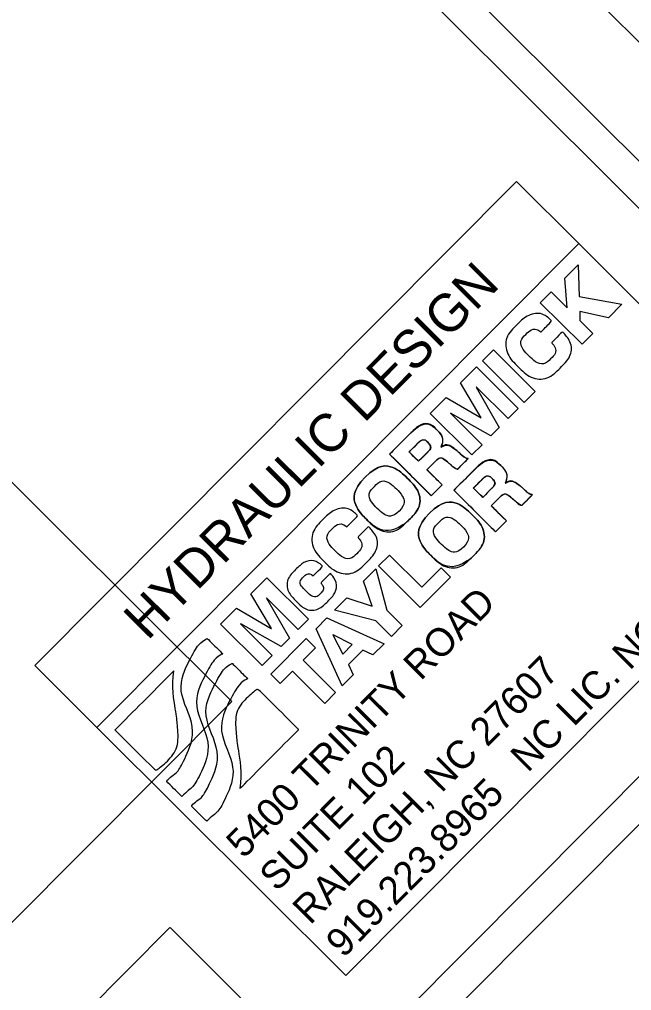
# Model space of a CAD drawing. Extents: x 1481763 to 1495577, y 493394 to 506245.
# Drawn here: x 1489913.5 to 1490186.2, y 499343.7 to 499776.1 of the extents above; entities that cross this region are included whole.
import ezdxf

# ---------------------------------------------------------------- set-up
doc = ezdxf.new("R2010")
doc.units = 0
for name, color, linetype in [('Prop Grid Mask', 7, 'Continuous'), ('Prop Horizontal Alignment Curve and Spiral Data', 7, 'Continuous'), ('Scratch_Level_4', 7, 'Continuous'), ('Sheet Plot Border Inside CELL', 7, 'Continuous'), ('Sheet Sticker Exception Certification CELL', 7, 'Continuous'), ('Sheet Title CELL', 7, 'Continuous')]:
    doc.layers.add(name, color=color, linetype=linetype)

msp = doc.modelspace()

# ---------------------------------------------------------------- linework, layer by layer
at = {"layer": 'Prop Grid Mask'}
for p, q in [((1490156.42, 499660.88), (1490162.4, 499666.89)), ((1490162.4, 499666.89), (1490162.87, 499652.75)), ((1490157.46, 499647.68), (1490156.42, 499660.88)), ((1490145.52, 499649.94), (1490150.34, 499654.78)), ((1490150.34, 499654.78), (1490157.46, 499647.68)), ((1490162.87, 499652.75), (1490181.82, 499649.26)), ((1490164.08, 499631.45), (1490145.52, 499649.94)), ((1490181.82, 499649.26), (1490175.84, 499643.26)), ((1490175.84, 499643.26), (1490163.07, 499646.03)), ((1490163.07, 499646.03), (1490163.18, 499641.99)), ((1490163.18, 499641.99), (1490168.9, 499636.29)), ((1490168.9, 499636.29), (1490164.08, 499631.45)), ((1490119.78, 499624.1), (1490124.6, 499628.93)), ((1490124.6, 499628.93), (1490143.16, 499610.44)), ((1490138.35, 499605.61), (1490119.78, 499624.1)), ((1490110, 499614.26), (1490117.09, 499621.39)), ((1490117.09, 499621.39), (1490135.65, 499602.9)), ((1490119.19, 499598.74), (1490110, 499614.26)), ((1490117.03, 499612.39), (1490116.98, 499612.33)), ((1490116.98, 499612.33), (1490127.19, 499594.4)), ((1490131.12, 499598.35), (1490117.03, 499612.39)), ((1490143.16, 499610.44), (1490138.35, 499605.61)), ((1490096.48, 499600.69), (1490103.58, 499607.82)), ((1490103.58, 499607.82), (1490119.13, 499598.69)), ((1490115.04, 499582.21), (1490096.48, 499600.69)), ((1490105.54, 499600.84), (1490105.48, 499600.79)), ((1490105.48, 499600.79), (1490119.57, 499586.76)), ((1490123.51, 499590.71), (1490105.54, 499600.84)), ((1490135.65, 499602.9), (1490131.12, 499598.35)), ((1490119.13, 499598.69), (1490119.19, 499598.74)), ((1490127.19, 499594.4), (1490123.51, 499590.71)), ((1490101.29, 499585.76), (1490101.34, 499585.71)), ((1490119.57, 499586.76), (1490115.04, 499582.21)), ((1490113.44, 499580.59), (1490108.67, 499575.81)), ((1490129.91, 499569.68), (1490129.96, 499569.63)), ((1490142.06, 499564.52), (1490137.29, 499559.74)), ((1490073.45, 499532.76), (1490078.27, 499537.59)), ((1490078.27, 499537.59), (1490092.67, 499523.25)), ((1490066.72, 499525.99), (1490072.18, 499531.48)), ((1490072.18, 499531.48), (1490077.1, 499513.12)), ((1490092.02, 499514.27), (1490073.45, 499532.76)), ((1490092.67, 499523.25), (1490101.3, 499531.91)), ((1490101.3, 499531.91), (1490105.45, 499527.76)), ((1490016.54, 499520.42), (1490023.64, 499527.55)), ((1490023.64, 499527.55), (1490042.2, 499509.06)), ((1490105.45, 499527.76), (1490092.02, 499514.27)), ((1490070.58, 499514.79), (1490066.72, 499525.99)), ((1490025.73, 499504.9), (1490016.54, 499520.42)), ((1490023.58, 499518.54), (1490023.53, 499518.49)), ((1490023.53, 499518.49), (1490033.73, 499500.56)), ((1490037.67, 499504.51), (1490023.58, 499518.54)), ((1490053.9, 499513.12), (1490059.37, 499518.61)), ((1490059.37, 499518.61), (1490070.58, 499514.79)), ((1490003.03, 499506.85), (1490010.12, 499513.98)), ((1490010.12, 499513.98), (1490025.68, 499504.85)), ((1490045.61, 499504.79), (1490050.5, 499509.71)), ((1490050.5, 499509.71), (1490075.98, 499498.16)), ((1490072.28, 499508.28), (1490053.9, 499513.12)), ((1490077.1, 499513.12), (1490084.01, 499506.23)), ((1490021.59, 499488.37), (1490003.03, 499506.85)), ((1490012.08, 499507), (1490012.03, 499506.95)), ((1490012.03, 499506.95), (1490026.12, 499492.92)), ((1490030.06, 499496.87), (1490012.08, 499507)), ((1490025.68, 499504.85), (1490025.73, 499504.9)), ((1490042.2, 499509.06), (1490037.67, 499504.51)), ((1490079.2, 499501.4), (1490072.28, 499508.28)), ((1490084.01, 499506.23), (1490079.2, 499501.4)), ((1490033.73, 499500.56), (1490030.06, 499496.87)), ((1490057.26, 499479.37), (1490045.61, 499504.79)), ((1490053.22, 499502.14), (1490053.16, 499502.09)), ((1490053.16, 499502.09), (1490057.57, 499493.51)), ((1490061.76, 499497.72), (1490053.22, 499502.14)), ((1490025.44, 499484.54), (1490041.28, 499500.45)), ((1490045.44, 499496.31), (1490039.93, 499490.77)), ((1490041.28, 499500.45), (1490045.44, 499496.31)), ((1490057.57, 499493.51), (1490061.76, 499497.72)), ((1490075.98, 499498.16), (1490070.95, 499493.12)), ((1490026.12, 499492.92), (1490021.59, 499488.37)), ((1490066.49, 499495.29), (1490060.04, 499488.82)), ((1490070.95, 499493.12), (1490066.49, 499495.29)), ((1490039.93, 499490.77), (1490054.33, 499476.42)), ((1490060.04, 499488.82), (1490062.2, 499484.33)), ((1490029.59, 499480.39), (1490025.44, 499484.54)), ((1490035.11, 499485.93), (1490029.59, 499480.39)), ((1490049.51, 499471.59), (1490035.11, 499485.93)), ((1490062.2, 499484.33), (1490057.26, 499479.37)), ((1490054.33, 499476.42), (1490049.51, 499471.59))]:
    msp.add_line(p, q, dxfattribs=at)
for points in [[(1489948.05, 499460.86), (1490162.62, 499676.33), (1490134.88, 499703.95), (1489920.31, 499488.48)], [(1489948.05, 499460.86), (1490162.62, 499676.33), (1490273.45, 499565.96), (1490058.87, 499350.49)]]:
    msp.add_lwpolyline(points, close=True, dxfattribs=at)
for points in [[(1490145.52, 499649.94), (1490150.34, 499654.78), (1490157.46, 499647.68), (1490156.42, 499660.88), (1490162.4, 499666.89), (1490162.87, 499652.75), (1490181.82, 499649.26), (1490175.84, 499643.26), (1490163.07, 499646.03), (1490163.18, 499641.99), (1490168.9, 499636.29), (1490164.08, 499631.45), (1490145.52, 499649.94)], [(1490119.78, 499624.1), (1490124.6, 499628.93), (1490143.16, 499610.44), (1490138.35, 499605.61), (1490119.78, 499624.1)], [(1490096.48, 499600.69), (1490103.58, 499607.82), (1490119.13, 499598.69), (1490119.19, 499598.74), (1490110, 499614.26), (1490117.09, 499621.39), (1490135.65, 499602.9), (1490131.12, 499598.35), (1490117.03, 499612.39), (1490116.98, 499612.33), (1490127.19, 499594.4), (1490123.51, 499590.71), (1490105.54, 499600.84), (1490105.48, 499600.79), (1490119.57, 499586.76), (1490115.04, 499582.21), (1490096.48, 499600.69)], [(1490098.68, 499579.29), (1490095.03, 499575.63), (1490101.79, 499568.89), (1490096.97, 499564.06), (1490078.41, 499582.55), (1490087.83, 499592.01)], [(1490090.93, 499587.37), (1490087.1, 499583.52), (1490091.28, 499579.35), (1490095.32, 499583.41)], [(1490127.3, 499563.22), (1490123.65, 499559.55), (1490130.41, 499552.82), (1490125.59, 499547.98), (1490107.03, 499566.47), (1490116.45, 499575.93)], [(1490119.55, 499571.3), (1490115.72, 499567.45), (1490119.9, 499563.28), (1490123.94, 499567.34)], [(1490073.45, 499532.76), (1490078.27, 499537.59), (1490092.67, 499523.25), (1490101.3, 499531.91), (1490105.45, 499527.76), (1490092.02, 499514.27), (1490073.45, 499532.76)], [(1490077.1, 499513.12), (1490084.01, 499506.23), (1490079.2, 499501.4), (1490072.28, 499508.28), (1490053.9, 499513.12), (1490059.37, 499518.61), (1490070.58, 499514.79), (1490066.72, 499525.99), (1490072.18, 499531.48), (1490077.1, 499513.12)], [(1490003.03, 499506.85), (1490010.12, 499513.98), (1490025.68, 499504.85), (1490025.73, 499504.9), (1490016.54, 499520.42), (1490023.64, 499527.55), (1490042.2, 499509.06), (1490037.67, 499504.51), (1490023.58, 499518.54), (1490023.53, 499518.49), (1490033.73, 499500.56), (1490030.06, 499496.87), (1490012.08, 499507), (1490012.03, 499506.95), (1490026.12, 499492.92), (1490021.59, 499488.37), (1490003.03, 499506.85)], [(1490045.61, 499504.79), (1490050.5, 499509.71), (1490075.98, 499498.16), (1490070.95, 499493.12), (1490066.49, 499495.29), (1490060.04, 499488.82), (1490062.2, 499484.33), (1490057.26, 499479.37), (1490045.61, 499504.79)], [(1490057.57, 499493.51), (1490061.76, 499497.72), (1490053.22, 499502.14), (1490053.16, 499502.09), (1490057.57, 499493.51)], [(1490045.44, 499496.31), (1490039.93, 499490.77), (1490054.33, 499476.42), (1490049.51, 499471.59), (1490035.11, 499485.93), (1490029.59, 499480.39), (1490025.44, 499484.54), (1490041.28, 499500.45), (1490045.44, 499496.31)]]:
    msp.add_lwpolyline(points, dxfattribs=at)
for points in [[(1490145.81, 499636.97), (1490143.68, 499638.57), (1490141.24, 499638.1), (1490139.22, 499636.07), (1490136.11, 499632.95), (1490137.68, 499629.01), (1490140.43, 499626.27), (1490143.19, 499623.52), (1490147.13, 499621.97), (1490150.24, 499625.09), (1490152.49, 499627.35), (1490152.49, 499629.95), (1490150.54, 499632.25), (1490150.54, 499632.25), (1490155.35, 499637.09), (1490155.35, 499637.09), (1490159.88, 499632.06), (1490159.19, 499625.76), (1490154.5, 499621.05), (1490148.91, 499615.44), (1490141, 499616.07), (1490135.62, 499621.43), (1490130.24, 499626.79), (1490129.57, 499634.7), (1490135.16, 499640.32), (1490139.15, 499644.32), (1490146.02, 499646.13), (1490150.62, 499641.8), (1490150.62, 499641.8), (1490145.81, 499636.97), (1490145.81, 499636.97)], [(1490145.81, 499636.97), (1490143.68, 499638.57), (1490141.24, 499638.1), (1490139.22, 499636.07), (1490136.11, 499632.95), (1490137.68, 499629.01), (1490140.43, 499626.27), (1490143.19, 499623.52), (1490147.13, 499621.97), (1490150.24, 499625.09), (1490152.49, 499627.35), (1490152.49, 499629.95), (1490150.54, 499632.25), (1490150.54, 499632.25), (1490155.35, 499637.09), (1490155.35, 499637.09), (1490159.88, 499632.06), (1490159.19, 499625.76), (1490154.5, 499621.05), (1490148.91, 499615.44), (1490141, 499616.07), (1490135.62, 499621.43), (1490130.24, 499626.79), (1490129.57, 499634.7), (1490135.16, 499640.32), (1490139.15, 499644.32), (1490146.02, 499646.13), (1490150.62, 499641.8), (1490150.62, 499641.8), (1490145.81, 499636.97), (1490145.81, 499636.97)], [(1490078.41, 499582.55), (1490078.41, 499582.55), (1490087.83, 499592.01), (1490087.83, 499592.01), (1490091.09, 499595.29), (1490095.79, 499597.03), (1490099.53, 499593.3), (1490101.53, 499591.31), (1490102.47, 499588.46), (1490101.29, 499585.76), (1490101.29, 499585.76), (1490101.34, 499585.71), (1490101.34, 499585.71), (1490103.77, 499587.22), (1490106.55, 499585.59), (1490108.48, 499583.98), (1490109.31, 499583.26), (1490112.11, 499580.62), (1490113.44, 499580.59), (1490113.44, 499580.59), (1490108.67, 499575.81), (1490108.67, 499575.81), (1490107.64, 499576.02), (1490105.74, 499577.75), (1490105.17, 499578.22), (1490103.16, 499579.95), (1490100.93, 499581.55), (1490098.68, 499579.29), (1490098.68, 499579.29), (1490095.03, 499575.63), (1490095.03, 499575.63), (1490095.03, 499575.63), (1490101.79, 499568.89), (1490101.79, 499568.89), (1490101.79, 499568.89), (1490096.97, 499564.06), (1490096.97, 499564.06), (1490096.97, 499564.06), (1490078.41, 499582.55), (1490078.41, 499582.55)], [(1490087.83, 499592.01), (1490091.09, 499595.29), (1490095.79, 499597.03), (1490099.53, 499593.3), (1490101.53, 499591.31), (1490102.47, 499588.46), (1490101.29, 499585.76)], [(1490091.28, 499579.35), (1490091.28, 499579.35), (1490095.32, 499583.41), (1490095.32, 499583.41), (1490096.77, 499584.87), (1490096.77, 499586.42), (1490095.36, 499587.82), (1490093.99, 499589.19), (1490092.27, 499588.72), (1490090.93, 499587.37), (1490090.93, 499587.37), (1490087.1, 499583.52), (1490087.1, 499583.52), (1490087.1, 499583.52), (1490091.28, 499579.35), (1490091.28, 499579.35)], [(1490095.32, 499583.41), (1490096.77, 499584.87), (1490096.77, 499586.42), (1490095.36, 499587.82), (1490093.99, 499589.19), (1490092.27, 499588.72), (1490090.93, 499587.37)], [(1490101.34, 499585.71), (1490103.77, 499587.22), (1490106.55, 499585.59), (1490108.48, 499583.98), (1490109.31, 499583.26), (1490112.11, 499580.62), (1490113.44, 499580.59)], [(1490108.67, 499575.81), (1490107.64, 499576.02), (1490105.74, 499577.75), (1490105.17, 499578.22), (1490103.16, 499579.95), (1490100.93, 499581.55), (1490098.68, 499579.29)], [(1490107.03, 499566.47), (1490107.03, 499566.47), (1490116.45, 499575.93), (1490116.45, 499575.93), (1490119.71, 499579.21), (1490124.41, 499580.96), (1490128.15, 499577.23), (1490130.15, 499575.23), (1490131.09, 499572.38), (1490129.91, 499569.68), (1490129.91, 499569.68), (1490129.96, 499569.63), (1490129.96, 499569.63), (1490132.39, 499571.14), (1490135.17, 499569.51), (1490137.09, 499567.91), (1490137.93, 499567.18), (1490140.73, 499564.54), (1490142.06, 499564.52), (1490142.06, 499564.52), (1490137.29, 499559.74), (1490137.29, 499559.74), (1490136.25, 499559.94), (1490134.36, 499561.67), (1490133.79, 499562.14), (1490131.78, 499563.87), (1490129.55, 499565.48), (1490127.3, 499563.22), (1490127.3, 499563.22), (1490123.65, 499559.55), (1490123.65, 499559.55), (1490123.65, 499559.55), (1490130.41, 499552.82), (1490130.41, 499552.82), (1490130.41, 499552.82), (1490125.59, 499547.98), (1490125.59, 499547.98), (1490125.59, 499547.98), (1490107.03, 499566.47), (1490107.03, 499566.47)], [(1490116.45, 499575.93), (1490119.71, 499579.21), (1490124.41, 499580.96), (1490128.15, 499577.23), (1490130.15, 499575.23), (1490131.09, 499572.38), (1490129.91, 499569.68)], [(1490067.47, 499572.35), (1490073.3, 499578.2), (1490080.88, 499577.22), (1490086.26, 499571.87), (1490091.64, 499566.51), (1490092.64, 499558.93), (1490086.82, 499553.08), (1490080.99, 499547.23), (1490073.41, 499548.2), (1490068.03, 499553.56), (1490062.65, 499558.92), (1490061.65, 499566.5), (1490067.47, 499572.35)], [(1490067.47, 499572.35), (1490073.3, 499578.2), (1490080.88, 499577.22), (1490086.26, 499571.87), (1490091.64, 499566.51), (1490092.64, 499558.93), (1490086.82, 499553.08), (1490086.02, 499552.28), (1490085.19, 499551.61), (1490084.33, 499551.06)], [(1490084.33, 499551.06), (1490078.96, 499547.58), (1490072.68, 499548.94), (1490068.03, 499553.56), (1490062.65, 499558.92), (1490061.65, 499566.5), (1490067.47, 499572.35)], [(1490082.66, 499557.23), (1490085.76, 499560.35), (1490084.2, 499564.29), (1490081.44, 499567.03), (1490078.69, 499569.78), (1490074.74, 499571.32), (1490071.63, 499568.2), (1490068.53, 499565.08), (1490070.09, 499561.14), (1490072.85, 499558.4), (1490075.6, 499555.65), (1490079.55, 499554.11), (1490082.66, 499557.23)], [(1490082.66, 499557.23), (1490085.76, 499560.35), (1490084.2, 499564.29), (1490081.44, 499567.03), (1490078.69, 499569.78), (1490074.74, 499571.32), (1490071.63, 499568.2), (1490068.53, 499565.08), (1490070.09, 499561.14), (1490072.85, 499558.4), (1490075.6, 499555.65), (1490079.55, 499554.11), (1490082.66, 499557.23)], [(1490119.9, 499563.28), (1490119.9, 499563.28), (1490123.94, 499567.34), (1490123.94, 499567.34), (1490125.39, 499568.79), (1490125.39, 499570.35), (1490123.99, 499571.75), (1490122.61, 499573.12), (1490120.9, 499572.65), (1490119.55, 499571.3), (1490119.55, 499571.3), (1490115.72, 499567.45), (1490115.72, 499567.45), (1490115.72, 499567.45), (1490119.9, 499563.28), (1490119.9, 499563.28)], [(1490123.94, 499567.34), (1490125.39, 499568.79), (1490125.39, 499570.35), (1490123.99, 499571.75), (1490122.61, 499573.12), (1490120.9, 499572.65), (1490119.55, 499571.3)], [(1490129.96, 499569.63), (1490132.39, 499571.14), (1490135.17, 499569.51), (1490137.09, 499567.91), (1490137.93, 499567.18), (1490140.73, 499564.54), (1490142.06, 499564.52)], [(1490137.29, 499559.74), (1490136.25, 499559.94), (1490134.36, 499561.67), (1490133.79, 499562.14), (1490131.78, 499563.87), (1490129.55, 499565.48), (1490127.3, 499563.22)], [(1490096.12, 499556.29), (1490101.94, 499562.14), (1490109.52, 499561.17), (1490114.9, 499555.82), (1490120.29, 499550.46), (1490121.29, 499542.88), (1490115.46, 499537.03), (1490109.64, 499531.18), (1490102.06, 499532.15), (1490096.68, 499537.51), (1490091.29, 499542.87), (1490090.29, 499550.45), (1490096.12, 499556.29)], [(1490096.12, 499556.29), (1490101.94, 499562.14), (1490109.52, 499561.17), (1490114.9, 499555.82), (1490120.29, 499550.46), (1490121.29, 499542.88), (1490115.46, 499537.03), (1490114.66, 499536.23), (1490113.83, 499535.56), (1490112.98, 499535.01)], [(1490059.45, 499550.25), (1490057.32, 499551.85), (1490054.88, 499551.38), (1490052.86, 499549.35), (1490049.76, 499546.23), (1490051.32, 499542.29), (1490054.08, 499539.55), (1490056.83, 499536.8), (1490060.78, 499535.26), (1490063.89, 499538.38), (1490066.14, 499540.64), (1490066.13, 499543.23), (1490064.18, 499545.54), (1490064.18, 499545.54), (1490069, 499550.37), (1490069, 499550.37), (1490073.52, 499545.35), (1490072.83, 499539.04), (1490068.15, 499534.34), (1490062.56, 499528.72), (1490054.64, 499529.35), (1490049.26, 499534.71), (1490043.88, 499540.07), (1490043.21, 499547.98), (1490048.8, 499553.6), (1490052.79, 499557.6), (1490059.66, 499559.41), (1490064.27, 499555.09), (1490064.27, 499555.09), (1490059.45, 499550.25), (1490059.45, 499550.25)], [(1490059.45, 499550.25), (1490057.32, 499551.85), (1490054.88, 499551.38), (1490052.86, 499549.35), (1490049.76, 499546.23), (1490051.32, 499542.29), (1490054.08, 499539.55), (1490056.83, 499536.8), (1490060.78, 499535.26), (1490063.89, 499538.38), (1490066.14, 499540.64), (1490066.13, 499543.23), (1490064.18, 499545.54), (1490064.18, 499545.54), (1490069, 499550.37), (1490069, 499550.37), (1490073.52, 499545.35), (1490072.83, 499539.04), (1490068.15, 499534.34), (1490062.56, 499528.72), (1490054.64, 499529.35), (1490049.26, 499534.71), (1490043.88, 499540.07), (1490043.21, 499547.98), (1490048.8, 499553.6), (1490052.79, 499557.6), (1490059.66, 499559.41), (1490064.27, 499555.09), (1490064.27, 499555.09), (1490059.45, 499550.25), (1490059.45, 499550.25)], [(1490112.98, 499535.01), (1490107.6, 499531.53), (1490101.32, 499532.89), (1490096.68, 499537.51), (1490091.29, 499542.87), (1490090.29, 499550.45), (1490096.12, 499556.29)], [(1490111.3, 499541.17), (1490114.41, 499544.29), (1490112.84, 499548.24), (1490110.09, 499550.98), (1490107.33, 499553.72), (1490103.39, 499555.27), (1490100.28, 499552.15), (1490097.17, 499549.03), (1490098.74, 499545.09), (1490101.49, 499542.35), (1490104.25, 499539.6), (1490108.19, 499538.05), (1490111.3, 499541.17)], [(1490111.3, 499541.17), (1490114.41, 499544.29), (1490112.84, 499548.24), (1490110.09, 499550.98), (1490107.33, 499553.72), (1490103.39, 499555.27), (1490100.28, 499552.15), (1490097.17, 499549.03), (1490098.74, 499545.09), (1490101.49, 499542.35), (1490104.25, 499539.6), (1490108.19, 499538.05), (1490111.3, 499541.17)], [(1490044.36, 499528.34), (1490043.19, 499529.45), (1490041.38, 499529.24), (1490040.26, 499528.12), (1490037.8, 499525.65), (1490039.52, 499523.16), (1490041.39, 499521.3), (1490043.13, 499519.57), (1490045.68, 499518.53), (1490047.54, 499520.41), (1490049.07, 499521.94), (1490048.96, 499523.6), (1490047.74, 499525.23), (1490047.74, 499525.23), (1490052.01, 499529.52), (1490052.01, 499529.52), (1490055.24, 499525.53), (1490054.52, 499520.65), (1490050.95, 499517.07), (1490046.91, 499513.01), (1490041.12, 499512.76), (1490036.99, 499516.88), (1490032.7, 499521.15), (1490032.35, 499526.94), (1490036.68, 499531.28), (1490040.02, 499534.63), (1490044.76, 499535.86), (1490048.63, 499532.63), (1490048.63, 499532.63), (1490044.36, 499528.34), (1490044.36, 499528.34)], [(1490044.36, 499528.34), (1490043.19, 499529.45), (1490041.38, 499529.24), (1490040.26, 499528.12), (1490037.8, 499525.65), (1490039.52, 499523.16), (1490041.39, 499521.3), (1490043.13, 499519.57), (1490045.68, 499518.53), (1490047.54, 499520.41), (1490049.07, 499521.94), (1490048.96, 499523.6), (1490047.74, 499525.23), (1490047.74, 499525.23), (1490052.01, 499529.52), (1490052.01, 499529.52), (1490055.24, 499525.53), (1490054.52, 499520.65), (1490050.95, 499517.07), (1490046.91, 499513.01), (1490041.12, 499512.76), (1490036.99, 499516.88), (1490032.7, 499521.15), (1490032.35, 499526.94), (1490036.68, 499531.28), (1490040.02, 499534.63), (1490044.76, 499535.86), (1490048.63, 499532.63), (1490048.63, 499532.63), (1490044.36, 499528.34), (1490044.36, 499528.34)], [(1489985.82, 499430.12), (1489988.19, 499432.5), (1489990.97, 499434.02), (1489994.06, 499439.95), (1490000.16, 499453.77), (1489989.58, 499470.77), (1489996.38, 499484.59), (1490000.25, 499491.57), (1490004.04, 499493.63), (1490004.04, 499493.63), (1490004.04, 499493.63), (1489997.17, 499500.47), (1489997.17, 499500.47), (1489997.17, 499500.47), (1489993.39, 499498.41), (1489989.51, 499491.43), (1489982.71, 499477.61), (1489993.29, 499460.61), (1489987.19, 499446.79), (1489984.1, 499440.85), (1489981.33, 499439.34), (1489978.95, 499436.96), (1489978.95, 499436.96), (1489985.82, 499430.12), (1489985.82, 499430.12)], [(1489985.82, 499430.12), (1489988.19, 499432.5), (1489990.97, 499434.02), (1489994.06, 499439.95), (1490000.16, 499453.77), (1489989.58, 499470.77), (1489996.38, 499484.59), (1490000.25, 499491.57), (1490004.04, 499493.63), (1490004.04, 499493.63), (1490004.04, 499493.63), (1489997.17, 499500.47), (1489997.17, 499500.47), (1489997.17, 499500.47), (1489993.39, 499498.41), (1489989.51, 499491.43), (1489982.71, 499477.61), (1489993.29, 499460.61), (1489987.19, 499446.79), (1489984.1, 499440.85), (1489981.33, 499439.34), (1489978.95, 499436.96), (1489978.95, 499436.96), (1489985.82, 499430.12), (1489985.82, 499430.12)], [(1489996.92, 499419.06), (1489999.3, 499421.44), (1490002.07, 499422.96), (1490005.16, 499428.89), (1490011.26, 499442.71), (1490000.68, 499459.71), (1490007.48, 499473.53), (1490011.36, 499480.52), (1490015.14, 499482.58), (1490015.14, 499482.58), (1490015.14, 499482.58), (1490008.27, 499489.42), (1490008.27, 499489.42), (1490008.27, 499489.42), (1490004.49, 499487.36), (1490000.61, 499480.37), (1489993.81, 499466.55), (1490004.39, 499449.55), (1489998.29, 499435.73), (1489995.2, 499429.8), (1489992.43, 499428.28), (1489990.05, 499425.9), (1489990.05, 499425.9), (1489996.92, 499419.06), (1489996.92, 499419.06)], [(1489996.92, 499419.06), (1489999.3, 499421.44), (1490002.07, 499422.96), (1490005.16, 499428.89), (1490011.26, 499442.71), (1490000.68, 499459.71), (1490007.48, 499473.53), (1490011.36, 499480.52), (1490015.14, 499482.58), (1490015.14, 499482.58), (1490015.14, 499482.58), (1490008.27, 499489.42), (1490008.27, 499489.42), (1490008.27, 499489.42), (1490004.49, 499487.36), (1490000.61, 499480.37), (1489993.81, 499466.55), (1490004.39, 499449.55), (1489998.29, 499435.73), (1489995.2, 499429.8), (1489992.43, 499428.28), (1489990.05, 499425.9), (1489990.05, 499425.9), (1489996.92, 499419.06), (1489996.92, 499419.06)], [(1489982.23, 499486.02), (1489981.18, 499479), (1489983.44, 499466.86), (1489983.81, 499462.73), (1489984.73, 499452.55), (1489980.36, 499446.35), (1489974.32, 499441.57), (1489974.32, 499441.57), (1489956.06, 499459.75), (1489956.06, 499459.75), (1489956.06, 499459.75), (1489982.23, 499486.02), (1489982.23, 499486.02)], [(1489982.23, 499486.02), (1489981.18, 499479), (1489983.44, 499466.86), (1489983.81, 499462.73), (1489984.73, 499452.55), (1489980.36, 499446.35), (1489974.32, 499441.57), (1489974.32, 499441.57), (1489956.06, 499459.75), (1489956.06, 499459.75), (1489956.06, 499459.75), (1489982.23, 499486.02), (1489982.23, 499486.02)], [(1490011.73, 499433.64), (1490012.77, 499440.67), (1490010.52, 499452.81), (1490010.15, 499456.93), (1490009.22, 499467.12), (1490013.6, 499473.32), (1490019.64, 499478.09), (1490019.64, 499478.09), (1490037.89, 499459.92), (1490037.89, 499459.92), (1490037.89, 499459.92), (1490011.73, 499433.64), (1490011.73, 499433.64)], [(1490011.73, 499433.64), (1490012.77, 499440.67), (1490010.52, 499452.81), (1490010.15, 499456.93), (1490009.22, 499467.12), (1490013.6, 499473.32), (1490019.64, 499478.09), (1490019.64, 499478.09), (1490037.89, 499459.92), (1490037.89, 499459.92), (1490037.89, 499459.92), (1490011.73, 499433.64), (1490011.73, 499433.64)]]:
    msp.add_open_spline(points, degree=3, dxfattribs=at)
at = {"layer": 'Scratch_Level_4'}
msp.add_lwpolyline([(1486945.73, 498451.82), (1488980.89, 500495.43), (1490008.12, 499472.43), (1487972.96, 497428.83)], close=True, dxfattribs=at)
at = {"layer": 'Sheet Plot Border Inside CELL'}
msp.add_lwpolyline([(1487337.48, 495550.45), (1490865.3, 499092.97), (1488622.45, 501326.52), (1485094.62, 497784)], close=True, dxfattribs=at)
at = {"layer": 'Sheet Sticker Exception Certification CELL'}
for p, q in [((1489669.38, 499059.29), (1489980.57, 499371.77)), ((1489980.59, 499371.74), (1490030.55, 499322))]:
    msp.add_line(p, q, dxfattribs=at)
at = {"layer": 'Sheet Title CELL'}
for p, q in [((1487288.78, 496526.16), (1490294.79, 499544.69)), ((1489976.81, 499204.13), (1490305.42, 499534.1))]:
    msp.add_line(p, q, dxfattribs=at)
for points in [[(1490709.17, 499195.53), (1488519.7, 501375.92)], [(1490294.73, 499587.09), (1488519.72, 501354.73)]]:
    msp.add_lwpolyline(points, dxfattribs=at)

# ---------------------------------------------------------------- texts
at = {"layer": 'Prop Grid Mask'}
for s, height, p in [('919.223.8965   NC LIC. NO. F-1285', 12.5355, (1490057.76, 499357.85)), ('5400 TRINITY ROAD', 12.5355, (1490013.35, 499402.08)), ('RALEIGH, NC 27607', 12.5355, (1490042.96, 499372.59)), ('SUITE 102', 12.536, (1490028.16, 499387.33))]:
    msp.add_text(s, height=height, rotation=45.1191, dxfattribs=at).set_placement(p)
at = {"layer": 'Prop Horizontal Alignment Curve and Spiral Data'}
msp.add_text('HYDRAULIC DESIGN', height=16.88, rotation=45.1191, dxfattribs=at).set_placement((1489970.53, 499499.21))

doc.saveas('drawing.dxf')
